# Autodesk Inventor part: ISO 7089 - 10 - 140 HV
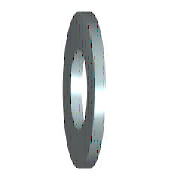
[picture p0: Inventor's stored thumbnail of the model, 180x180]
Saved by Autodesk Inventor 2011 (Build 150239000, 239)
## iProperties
IsCustomPart: 0
Created: 2009-02
Part Number: ISO 7089 - 10 - 140 HV
Material: Stainless Steel
Description: Plain washers - Normal series - Product grade A
Document SubType Name: Modeling
Standard: ISO 7089
Designer: V.de Jong
Standard Revision: Second edition 2000-06-01
Standards Organization: ISO
Language: en-US
Size Designation: 10 - 140 HV
Categories: <MemberInstance><Categories><Category DisplayName="Fasteners" InternalName="e4da775c-781d-43d5-af7c-5136215cf5a6" Mnemonic="FSTN"><Category DisplayName="Washers
Density: 8.08 g/cm^3
Mass: 3.67752 g
Surface Area: 6.46775 cm^2
Volume: 0.455138 cm^3
Author: V.de Jong
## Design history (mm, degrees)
body "Solid1"
sketch "Sketch"
  geometry: C1 r 10 at (0, 0); C2 r 5.25 at (0, 0); 1 further point
  constraints: 2 centre point, 2 coincident
  dimensions: "d0" = 10.5 diameter of C2 (= SD1); "d1" = 20 diameter of C1 (= SD2)
extrude "Body" new body sketch "Sketch" distance "d2" = 2 (= SD); taper "d3" = 0 deg
workaxis "Work Axis1"
workplane "Work Plane1"
other parameters: "SD1" = 10.5 [user parameter; used in 1 equation term], "SD2" = 20 [user parameter; used in 1 equation term], "SD" = 2 [user parameter; used in 1 equation term], "d4" = 0, "d5" = 0, "d6" = 0, "d7" = 0
